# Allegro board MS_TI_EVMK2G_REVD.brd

Outline 305.63 x 258 mm; copper layers: TOP, L02_GND1, L03_SIG1, L04_GND2, L05_PWR1, L06_PWR2, L07_GND3, L08_SIG2, L09_GND4, BOTTOM. Coordinates in mm from the lower left corner of the outline.
Outline path: 0,7 1.27,7 ; 0.64,251 0.64,256.8 arc(0.99,257.65) 1.83,258 304.43,258 arc(305.28,257.65) 305.63,256.8 305.63,251 ; 0.64,251 305.63,251 ; 0.64,251 0.64,7 ; 305.63,251 305.63,7 ; 0.64,7 0.64,1.2 arc(0.99,0.35) 1.83,0 304.43,0 arc(305.28,0.35) 305.63,1.2 305.63,7 ; 0.64,7 305.63,7 ; 0.64,6.36 0.64,7.63 ; 77.68,7 77.68,5 95.41,5 95.41,7 ; 159.66,7 159.66,4.97 159.67,4.97 182.04,4.97 182.04,6.93 ; 188.99,7 188.99,4.97 200.5,4.97 200.5,7 ; 207.02,7.05 207.02,5.03 224.66,5.03 224.66,7.05 ; 231.49,7 231.49,4.97 293.03,4.97 293.03,7

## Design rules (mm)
net group 1P8V_EN: nets 1P8V_EN N20088355
net group 24MHZ_LVCMOS_USB0_CLK: nets 24MHZ_LVCMOS_USB0_CLK SOC_USB0_XO
net group 24MHZ_LVCMOS_USB1_CLK: nets 24MHZ_LVCMOS_USB1_CLK SOC_USB1_XO
net group 24MHZ_LVDS_N: nets 24MHZ_LVDS_N SOC_SYSCLKN
net group 24MHZ_LVDS_P: nets 24MHZ_LVDS_P SOC_SYSCLKP
net group 100MHZ_HCSL: nets 100MHZ_HCSL_N 100MHZ_HCSL_P
net group 100MHZ_LVDS_N: nets 100MHZ_LVDS_N DDR_CLKN_LVDS_100MHZ
net group 100MHZ_LVDS_P: nets 100MHZ_LVDS_P DDR_CLKP_LVDS_100MHZ
net group 250MHZ_LVDS_CPTS_REF_CLKN: nets 250MHZ_LVDS_CPTS_REF_CLKN 250MHZ_LVDS_N
net group 250MHZ_LVDS_CPTS_REF_CLKP: nets 250MHZ_LVDS_CPTS_REF_CLKP 250MHZ_LVDS_P
net group BMC_BLUE_LED: nets BMC_BLUE_LED N14119383
net group BMC_GPIO0: nets BMC_GPIO0 N19771684
net group BMC_GPIO1: nets BMC_GPIO1 N19771691
net group BMC_GPIO3: nets BMC_GPIO3 N19771705
net group BMC_GPIO4: nets BMC_GPIO4 N19771712
net group BMC_GPIO5: nets BMC_GPIO5 N19771719
net group BMC_GPIO6: nets BMC_GPIO6 N19771726
net group BMC_GREEN_LED: nets BMC_GREEN_LED N14119875
net group BMC_I2C1_SCL: nets BMC_I2C1_SCL N19935623
net group BMC_I2C1_SDA: nets BMC_I2C1_SDA N19935654
net group BMC_SPI0_CLK: nets BMC_SPI0_CLK N19776412
net group BMC_UART1_RX: nets BMC_UART1_RX N20334677
net group BMC_UART1_TX: nets BMC_UART1_TX N20334698
net group BMC_XOSC0: nets BMC_XOSC0 BMC_XOSC0_R
net group BUF_ETH_RSTN: nets BUF_ETH_RSTN ETH_RSTN_AND
net group BUF_I2C1_SCL: nets BUF_I2C1_SCL N19351417
net group BUF_I2C1_SDA: nets BUF_I2C1_SDA N19351424
net group BUF_MCASP2AXR3: nets BUF_MCASP2AXR3 N14061510
net group BUF_MIPI_TCK: nets BUF_MIPI_TCK N23802386
net group BUF_TXVR_RXD: nets BUF_TXVR_RXD N16801982
net group BUF_TXVR_TXD: nets BUF_TXVR_TXD N16801984
net group BUF_XDS_TCK: nets BUF_XDS_TCK N18323233
net group BUFF_DSS_DE: nets BUFF_DSS_DE SOC_DSS_DE
net group BUFF_DSSDATA0: nets BUFF_DSSDATA0 SOC_DSSDATA0
net group BUFF_DSSDATA1: nets BUFF_DSSDATA1 SOC_DSSDATA1
net group BUFF_DSSDATA2: nets BUFF_DSSDATA2 SOC_DSSDATA2
net group BUFF_DSSDATA3: nets BUFF_DSSDATA3 SOC_DSSDATA3
net group BUFF_DSSDATA4: nets BUFF_DSSDATA4 SOC_DSSDATA4
net group BUFF_DSSDATA5: nets BUFF_DSSDATA5 SOC_DSSDATA5
net group BUFF_DSSHSYNC: nets BUFF_DSSHSYNC SOC_DSSHSYNC
net group BUFF_DSSPCLK: nets BUFF_DSSPCLK SOC_DSSPCLK
net group BUFF_DSSVSYNC: nets BUFF_DSSVSYNC SOC_DSSVSYNC
net group CAN1: nets N19508331 N19508333
net group COM_AUD_CLK: nets COM_AUD_CLK WL_MCASP2_ACLKR
net group COM_AUD_FSYNC: nets COM_AUD_FSYNC WL_MCASP2_FSR
net group COM_AUD_IN: nets COM_AUD_IN WL_MCASP2_AXR1
net group COM_AUD_OUT: nets COM_AUD_OUT WL_MCASP2_AXR4
net group COM_BTRST: nets COM_BTRST WL_BT_EN
net group COM_BTUARTCTS: nets COM_BTUARTCTS WL_UART1_RTSN
net group COM_BTUARTRTS: nets COM_BTUARTRTS WL_UART1_CTSN
net group COM_BTUARTRX: nets COM_BTUARTRX WL_UART1_TXD
net group COM_BTUARTTX: nets COM_BTUARTTX WL_UART1_RXD
net group COM_SLOW_CLK: nets COM_SLOW_CLK WL_WLAN_CLK
net group COM_WL_IRQ: nets COM_WL_IRQ WL_WLAN_IRQ
net group COM_WL_RST: nets COM_WL_RST WL_WLAN_EN
net group CPLD_A0: nets CPLD_A0 EMA_A0
net group CPLD_A1: nets CPLD_A1 EMA_A1
net group CPLD_A2: nets CPLD_A2 EMA_A2
net group CPLD_A3: nets CPLD_A3 EMA_A3
net group CPLD_BIO_0: nets CPLD_BIO_0 GP4-0
net group CPLD_BIO_1: nets CPLD_BIO_1 GP4-1
net group CPLD_BIO_2: nets CPLD_BIO_2 GP4-2
net group CPLD_CSN: nets CPLD_CSN N17109206
net group CPLD_D0: nets CPLD_D0 EMA_D0
net group CPLD_D1: nets CPLD_D1 EMA_D1
net group CPLD_RDN: nets CPLD_RDN N17108922
net group CPLD_TCK: nets CPLD_TCK N17113205
net group CPLD_WEN: nets CPLD_WEN N17108924
net group CVDD_EN: nets CVDD_EN N20088352
net group DAT4: nets DAT4 SOC_MMC1_DAT4
net group DAT5: nets DAT5 SOC_MMC1_DAT5
net group DAT6: nets DAT6 SOC_MMC1_DAT6
net group DAT7: nets DAT7 SOC_MMC1_DAT7
net group DBG_EMU0: nets DBG_EMU0 N21115682
net group DBG_EMU1: nets DBG_EMU1 N21115817
net group DBG_RTCK: nets DBG_RTCK RTCK/GP8[0]
net group DIFFPAIR2: nets CP2105_DM CP2105_DP
net group DP1: nets N19508261 N19508263
net group DP3: nets N19510567 N19510569
net group EMA_A4: nets EMA_A4 MEM_A4
net group EMA_A5: nets EMA_A5 MEM_A5
net group EMA_A6: nets EMA_A6 MEM_A6
net group EMA_A7: nets EMA_A7 MEM_A7
net group EMA_A8: nets EMA_A8 MEM_A8
net group EMA_A9: nets EMA_A9 MEM_A9
net group EMA_A10: nets EMA_A10 MEM_A10
net group EMA_A11: nets EMA_A11 MEM_A11
net group EMA_A12: nets EMA_A12 MEM_A12
net group EMA_BA0: nets EMA_BA0 MEM_BA0
net group EMA_BA1: nets EMA_BA1 MEM_BA1
net group EMA_D2: nets EMA_D2 MEM_D2
net group EMA_D3: nets EMA_D3 MEM_D3
net group EMA_D4: nets EMA_D4 MEM_D4
net group EMA_D5: nets EMA_D5 MEM_D5
net group EMA_D6: nets EMA_D6 MEM_D6
net group EMA_D7: nets EMA_D7 MEM_D7
net group EMA_D8: nets EMA_D8 MEM_D8
net group EMA_D9: nets EMA_D9 MEM_D9
net group EMA_D10: nets EMA_D10 MEM_D10
net group EMA_D11: nets EMA_D11 MEM_D11
net group EMA_D12: nets EMA_D12 MEM_D12
net group EMA_D13: nets EMA_D13 MEM_D13
net group EMA_D14: nets EMA_D14 MEM_D14
net group EMA_D15: nets EMA_D15 MEM_D15
net group GND: nets PLL0_VSSA PLL1_VSSA
net group HDMI_CLK: nets HDMI_CLK+ HDMI_CLK-
net group HDMI_TX0: nets HDMI_TX0+ HDMI_TX0-
net group HDMI_TX1: nets HDMI_TX1+ HDMI_TX1-
net group HDMI_TX2: nets HDMI_TX2+ HDMI_TX2-
net group LCD_DCLK: nets LCD_DCLK N20247908
net group LCD_EN: nets LCD_EN N20391651
net group LCD_HD: nets LCD_HD N17473267
net group LCD_VD: nets LCD_VD N20273568
net group MEM_CASN: nets MEM_CASN N17108899
net group MEM_CKE: nets MEM_CKE N17110913
net group MEM_CLK: nets MEM_CLK N17110905
net group MEM_CS0N: nets MEM_CS0N N17108888
net group MEM_RASN: nets MEM_RASN N17110918
net group MEM_WE_DQM0N: nets MEM_WE_DQM0N N17109930
net group MEM_WE_DQM1N: nets MEM_WE_DQM1N N17109932
net group MIPI_EMU_RTCK: nets MIPI_EMU_RTCK MIPI_RTCK
net group MIPI_TDI: nets MIPI_TDI MIPI_TDI_R
net group MIPI_TDO: nets MIPI_TDO MIPI_TDO_R
net group MIPI_TMS: nets MIPI_TMS MIPI_TMS_R
net group MIPI_TRGRSTZ: nets MIPI_TRGRSTZ N17217348
net group MIPI_TRST#: nets MIPI_TRST# MIPI_TRST#_R
net group N14115400: nets N14115400 N20324951
net group N16781633: nets N16781633 N16781680
net group N17255053: nets N17255053 N17255055
net group N17255071: nets N17255071 N17255073
net group N17556024: nets N17556024 N17557462
net group N17556776: nets N17556776 N17556884
net group N18024893: nets N18024893 N20324932
net group N19636243: nets N19636243 N19636350
net group N19636273: nets N19636273 N19636291
net group N21997071: nets N21997071 N21997073
net group NRESPWRON2: nets N20088492 NRESPWRON2
net group PCI_CON_PORZ: nets N18214699 PCI_CON_PORZ
net group PCIE_CLK_HCSL_100MHZ: nets PCIE_CLKN_HCSL_100MHZ PCIE_CLKP_HCSL_100MHZ
net group PCIE_CLKN_CML_100MHZ: nets N22048912 PCIE_CLKN_CML_100MHZ
net group PCIE_CLKP_CML_100MHZ: nets N22048902 PCIE_CLKP_CML_100MHZ
net group PCIEI_RSTN: nets N18211886 PCIEI_RSTN
net group PMIC_GPIO2: nets N20088340 PMIC_GPIO2
net group SD_LP2996A: nets N21320308 SD_LP2996A
net group SEC_REFN: nets N21185356 SEC_REFN
net group SEC_REFP: nets N21185385 SEC_REFP
net group SEL_HDMIN: nets SEL_HDMIN SEL_HDMIN_GPIO
net group SOC_MCASP0ACLKR: nets N19368179 SOC_MCASP0ACLKR
net group SOC_MCASP0ACLKX: nets N19368284 SOC_MCASP0ACLKX
net group SOC_MCASP0AHCLKR: nets N19368226 SOC_MCASP0AHCLKR
net group SOC_MCASP0AMUTE: nets N19367970 SOC_MCASP0AMUTE
net group SOC_MCASP0AXR0: nets N19367736 SOC_MCASP0AXR0
net group SOC_MCASP0AXR1: nets N19367738 SOC_MCASP0AXR1
net group SOC_MCASP0AXR2: nets N19367748 SOC_MCASP0AXR2
net group SOC_MCASP0AXR3: nets N19367766 SOC_MCASP0AXR3
net group SOC_MCASP0AXR4: nets N19367768 SOC_MCASP0AXR4
net group SOC_MCASP0AXR5: nets N19367778 SOC_MCASP0AXR5
net group SOC_MCASP0AXR6: nets N19367788 SOC_MCASP0AXR6
net group SOC_MCASP0AXR7: nets N19367798 SOC_MCASP0AXR7
net group SOC_MCASP0AXR8: nets N19367816 SOC_MCASP0AXR8
net group SOC_MCASP0AXR9: nets N19367818 SOC_MCASP0AXR9
net group SOC_MCASP0AXR12: nets N19367846 SOC_MCASP0AXR12
net group SOC_MCASP0AXR13: nets N19367848 SOC_MCASP0AXR13
net group SOC_MCASP0AXR14: nets N19367866 SOC_MCASP0AXR14
net group SOC_MCASP0AXR15: nets N19367868 SOC_MCASP0AXR15
net group SOC_MCASP0FSR: nets N19368123 SOC_MCASP0FSR
net group SOC_MCASP0FSX: nets N19368147 SOC_MCASP0FSX
net group SOC_MCASP1ACLKR: nets N19368850 SOC_MCASP1ACLKR
net group SOC_MCASP1ACLKX: nets N19368786 SOC_MCASP1ACLKX
net group SOC_MCASP1AHCLKR: nets N19368882 SOC_MCASP1AHCLKR
net group SOC_MCASP1AXR0: nets N19368587 SOC_MCASP1AXR0
net group SOC_MCASP1AXR1: nets N19368605 SOC_MCASP1AXR1
net group SOC_MCASP1AXR2: nets N19368607 SOC_MCASP1AXR2
net group SOC_MCASP1AXR3: nets N19368625 SOC_MCASP1AXR3
net group SOC_MCASP1AXR4: nets N19368627 SOC_MCASP1AXR4
net group SOC_MCASP1AXR5: nets N19368645 SOC_MCASP1AXR5
net group SOC_MCASP1AXR6: nets N19368655 SOC_MCASP1AXR6
net group SOC_MCASP1AXR7: nets N19368657 SOC_MCASP1AXR7
net group SOC_MCASP1AXR8: nets N19368675 SOC_MCASP1AXR8
net group SOC_MCASP1AXR9: nets N19368677 SOC_MCASP1AXR9
net group SOC_MCASP1FSR: nets N19368946 SOC_MCASP1FSR
net group SOC_MCASP1FSX: nets N19368978 SOC_MCASP1FSX
net group SOC_MCASP2ACLKR: nets N19369349 SOC_MCASP2ACLKR
net group SOC_MCASP2ACLKX: nets N19369390 SOC_MCASP2ACLKX
net group SOC_MCASP2AHCLKR: nets N19369435 SOC_MCASP2AHCLKR
net group SOC_MCASP2AHCLKX: nets N19369467 SOC_MCASP2AHCLKX
net group SOC_MCASP2AXR1: nets N19369157 SOC_MCASP2AXR1
net group SOC_MCASP2AXR2: nets N19369167 SOC_MCASP2AXR2
net group SOC_MCASP2AXR3: nets N19369177 SOC_MCASP2AXR3
net group SOC_MCASP2AXR4: nets N19369187 SOC_MCASP2AXR4
net group SOC_MCASP2AXR5: nets N19369197 SOC_MCASP2AXR5
net group SOC_MCASP2FSR: nets N19369503 SOC_MCASP2FSR
net group SOC_MCASP2FSX: nets N19369544 SOC_MCASP2FSX
net group SOC_MLB_PCLK: nets SOC_MLB_PCLKN SOC_MLB_PCLKP
net group SOC_MLB_PDATD: nets SOC_MLB_PDATDN SOC_MLB_PDATDP
net group SOC_MMC0_CLK: nets SOC_MMC0_CLK SOC_MMC0_CLK_R
net group SOC_MMC0_CMD: nets SOC_MMC0_CMD SOC_MMC0_CMD_R
net group SOC_MMC0_DAT0: nets SOC_MMC0_DAT0 SOC_MMC0_DAT0_R
net group SOC_MMC0_DAT1: nets SOC_MMC0_DAT1 SOC_MMC0_DAT1_R
net group SOC_MMC0_DAT2: nets SOC_MMC0_DAT2 SOC_MMC0_DAT2_R
net group SOC_MMC0_DAT3: nets SOC_MMC0_DAT3 SOC_MMC0_DAT3_R
net group SOC_PCIE_RXN0: nets SOC_PCIE_RXN0 SOC_PCIE_RXN0_C
net group SOC_PCIE_RXP0: nets SOC_PCIE_RXP0 SOC_PCIE_RXP0_C
net group SOC_PCIE_TX: nets SOC_PCIE_TXN0 SOC_PCIE_TXP0
net group SOC_PCIE_TX_C: nets SOC_PCIE_TXN0_C SOC_PCIE_TXP0_C
net group SOC_PLL_LOCK: nets N19749727 SOC_PLL_LOCK
net group SOC_RESETSTATZ: nets N19749933 SOC_RESETSTATZ
net group SOC_RGMII_RXCLK: nets SOC_RGMII_RXCLK SOC_RGMII_RXCLK_R
net group SOC_RGMII_RXCTL: nets SOC_RGMII_RXCTL SOC_RGMII_RXCTL_R
net group SOC_RGMII_RXD0: nets SOC_RGMII_RXD0 SOC_RGMII_RXD0_R
net group SOC_RGMII_RXD1: nets SOC_RGMII_RXD1 SOC_RGMII_RXD1_R
net group SOC_RGMII_RXD2: nets SOC_RGMII_RXD2 SOC_RGMII_RXD2_R
net group SOC_RGMII_RXD3: nets SOC_RGMII_RXD3 SOC_RGMII_RXD3_R
net group SOC_RGMII_TXCLK: nets SOC_RGMII_TXCLK SOC_RGMII_TXCLK_R
net group SOC_RGMII_TXCTL: nets SOC_RGMII_TXCTL SOC_RGMII_TXCTL_R
net group SOC_RGMII_TXD0: nets SOC_RGMII_TXD0 SOC_RGMII_TXD0_R
net group SOC_RGMII_TXD1: nets SOC_RGMII_TXD1 SOC_RGMII_TXD1_R
net group SOC_RGMII_TXD2: nets SOC_RGMII_TXD2 SOC_RGMII_TXD2_R
net group SOC_RGMII_TXD3: nets SOC_RGMII_TXD3 SOC_RGMII_TXD3_R
net group SOC_SPI0_CLK: nets N19935221 SOC_SPI0_CLK
net group SOC_SPI1_CLK: nets SOC_SPI1_CLK SOC_SPI1_CLK_R
net group SOC_SPI2_CLK: nets N19935328 SOC_SPI2_CLK
net group SOC_SPI3_CLK: nets N19776321 SOC_SPI3_CLK
net group SOC_SPI3_SCS0: nets SOC_SPI3_SCS0 SOC_SPI3_SCS0_R
net group SOC_USB1_ID: nets SOC_USB1_ID USB1_CONN_ID
net group T_RTCK: nets T_RTCK URTCK
net group T_TCK: nets T_TCK UTCK
net group T_TDI: nets T_TDI UTDI
net group T_TDIS: nets T_TDIS UTDIS
net group T_TMS: nets T_TMS UTMS
net group T_TRST_N: nets T_TRST_N UTRSTN
net group TPS_INT1: nets N20088495 TPS_INT1
net group UART0_TXVR_EN: nets N18091435 UART0_TXVR_EN
net group USB1_: nets USB0_CONN_DM USB0_CONN_DP
net group UTDO: nets UTDO XDS200_TDO
net group VCC3V3_LCD: nets N16781762 VCC3V3_LCD
net group VCC5V0_LCD: nets N16781794 VCC5V0_LCD
net group VHDMI_IOVCC: nets N14056401 VHDMI_IOVCC
net group XDS200_SPI1_CLK: nets N17255146 XDS200_SPI1_CLK
net group XDS_SYS_RESETN: nets N17289768 XDS_SYS_RESETN
net group AUD_MCLK_R: nets AUD_MCLK_R HDMI_AUDIO_MSTRCLK N22896196
net group BMC_I2C0_SCL: nets BMC_I2C0_SCL N19643490 PMBUS_SCL
net group BMC_I2C0_SDA: nets BMC_I2C0_SDA N19643422 PMBUS_SDA
net group BMC_JTAG_TCK: nets BMC_JTAG_TCK JTAG_RTCK N14084176
net group BMC_SPI0_MISO: nets BMC_SPI0_MISO BMC_SPI0_MOSI N17177920 N18163620
net group BMC_SPI1_MOSI: nets BMC_SPI1_MOSI N18029281 N18029296
net group BUF_MMC1_CLK: nets BUF_MMC1_CLK N26217961 SOC_MMC1_CLK SOC_MMC1_CLK_R
net group BUF_MMC1_CMD: nets BUF_MMC1_CMD N26217993 SOC_MMC1_CMD SOC_MMC1_CMD_R
net group BUF_MMC1_DAT0: nets BUF_MMC1_DAT0 DAT0 SOC_MMC1_DAT0 SOC_MMC1_DAT0_R
net group BUF_MMC1_DAT1: nets BUF_MMC1_DAT1 DAT1 SOC_MMC1_DAT1 SOC_MMC1_DAT1_R
net group BUF_MMC1_DAT2: nets BUF_MMC1_DAT2 DAT2 SOC_MMC1_DAT2 SOC_MMC1_DAT2_R
net group BUF_MMC1_DAT3: nets BUF_MMC1_DAT3 DAT3 SOC_MMC1_DAT3 SOC_MMC1_DAT3_R
net group BUFF_DSSDATA6: nets BUFF_DSSDATA6 MIPI_EMU19 SOC_DSSDATA6
net group BUFF_DSSDATA7: nets BUFF_DSSDATA7 MIPI_EMU18 SOC_DSSDATA7
net group BUFF_DSSDATA8: nets BUFF_DSSDATA8 MIPI_EMU17 SOC_DSSDATA8
net group BUFF_DSSDATA9: nets BUFF_DSSDATA9 MIPI_EMU16 SOC_DSSDATA9
net group BUFF_DSSDATA10: nets BUFF_DSSDATA10 MIPI_EMU15 SOC_DSSDATA10
net group BUFF_DSSDATA11: nets BUFF_DSSDATA11 MIPI_EMU14 SOC_DSSDATA11
net group BUFF_DSSDATA12: nets BUFF_DSSDATA12 MIPI_EMU13 SOC_DSSDATA12
net group BUFF_DSSDATA13: nets BUFF_DSSDATA13 MIPI_EMU12 SOC_DSSDATA13
net group BUFF_DSSDATA14: nets BUFF_DSSDATA14 MIPI_EMU11 SOC_DSSDATA14
net group BUFF_DSSDATA15: nets BUFF_DSSDATA15 MIPI_EMU10 SOC_DSSDATA15
net group BUFF_DSSDATA16: nets BUFF_DSSDATA16 MIPI_EMU09 SOC_DSSDATA16
net group BUFF_DSSDATA17: nets BUFF_DSSDATA17 MIPI_EMU08 SOC_DSSDATA17
net group BUFF_DSSDATA18: nets BUFF_DSSDATA18 MIPI_EMU07 SOC_DSSDATA18
net group BUFF_DSSDATA19: nets BUFF_DSSDATA19 MIPI_EMU06 SOC_DSSDATA19
net group BUFF_DSSDATA20: nets BUFF_DSSDATA20 MIPI_EMU05 SOC_DSSDATA20
net group BUFF_DSSDATA21: nets BUFF_DSSDATA21 MIPI_EMU04 SOC_DSSDATA21
net group BUFF_DSSDATA22: nets BUFF_DSSDATA22 MIPI_EMU03 SOC_DSSDATA22
net group BUFF_DSSDATA23: nets BUFF_DSSDATA23 MIPI_EMU02 SOC_DSSDATA23
net group CLK32KOUT: nets CLK32KOUT N19442104 WLAN_SLOW_CLK
net group CPLD_BIO_3: nets CPLD_BIO_3 CPLD_TXD1 GP4-3
net group CPLD_BIO_4: nets CPLD_BIO_4 CPLD_RXD1 GP4-4
net group CS2000_CLKIN: nets CS2000_CLKIN SOC_CPTS_TS_COMP SOC_MCASP1AMUTE SOC_MCASP1AMUTE_R
net group DC_BRD_DET: nets DC_BRD_DET N20333845 N22525689 N24555288
net group DDR_DB0: nets DDR_DM0 DDR_DQ0 DDR_DQ1 DDR_DQ2 DDR_DQ3 DDR_DQ4 DDR_DQ5 DDR_DQ6 DDR_DQ7 DDR_DQS0 DDR_DQS0#
net group DDR_DB1: nets DDR_DM1 DDR_DQ8 DDR_DQ9 DDR_DQ10 DDR_DQ11 DDR_DQ12 DDR_DQ13 DDR_DQ14 DDR_DQ15 DDR_DQS1 DDR_DQS1#
net group DDR_DB2: nets DDR_DM2 DDR_DQ16 DDR_DQ17 DDR_DQ18 DDR_DQ19 DDR_DQ20 DDR_DQ21 DDR_DQ22 DDR_DQ23 DDR_DQS2 DDR_DQS2#
net group DDR_DB3: nets DDR_DM3 DDR_DQ24 DDR_DQ25 DDR_DQ26 DDR_DQ27 DDR_DQ28 DDR_DQ29 DDR_DQ30 DDR_DQ31 DDR_DQS3 DDR_DQS3#
net group DDR_DB4: nets DDR_CB00 DDR_CB01 DDR_CB02 DDR_CB03 DDR_CBDQM DDR_CBDQS DDR_CBDQS#
net group DISP_EN: nets DISP_EN SEL_LCD SEL_LCDN SEL_LCDN_GPIO
net group ETHER1_D0_D3: nets ETHER1_D0N ETHER1_D0P ETHER1_D1N ETHER1_D1P ETHER1_D2N ETHER1_D2P ETHER1_D3N ETHER1_D3P
net group HDMI-RGB: nets HDMI_AC_BIAS_EN HDMI_DATA0 HDMI_DATA1 HDMI_DATA2 HDMI_DATA3 HDMI_DATA4 HDMI_DATA5 HDMI_DATA6 HDMI_DATA7 HDMI_DATA8 HDMI_DATA9 HDMI_DATA10 HDMI_DATA11 HDMI_DATA12 HDMI_DATA13 HDMI_DATA14 HDMI_DATA15 HDMI_DATA16 HDMI_DATA17 HDMI_DATA18 HDMI_DATA19 HDMI_DATA20 HDMI_DATA21 HDMI_DATA22 HDMI_DATA23 HDMI_HSYNC HDMI_PCLK HDMI_VSYNC
net group INA_ALERT: nets INA_ALERT N21783594 N21786150 N21786851 N21787536 N21787552
net group LCD: nets LCD_BLUE0 LCD_BLUE1 LCD_BLUE2 LCD_BLUE3 LCD_BLUE4 LCD_BLUE5 LCD_BLUE6 LCD_BLUE7 LCD_GREEN0 LCD_GREEN1 LCD_GREEN2 LCD_GREEN3 LCD_GREEN4 LCD_GREEN5 LCD_GREEN6 LCD_GREEN7 LCD_RED0 LCD_RED1 LCD_RED2 LCD_RED3 LCD_RED4 LCD_RED5 LCD_RED6 LCD_RED7
net group MIPI_TCK: nets MIPI_TCK MIPI_TCK_R SEL_XDS200_INV SOC_TDI SOC_TDO SOC_TMS VCC3V3_MIPI
net group N14092548: nets N14092548
net group N21505605: nets N21505605 N21505608 N21505611
net group PENDING_NETS: nets AUDIO_RSTN AUDIO_RSTN_AND BMC_HIBN BMC_INT1 BMC_ISOL_EN1 BMC_ISOL_EN2 BMC_ISOL_EN3 BMC_ISOL_EN4 BMC_ISOL_EN5 BMC_JTAG_TDI BMC_JTAG_TDO BMC_JTAG_TMS BMC_JTAG_TRSTN BMC_LCD_A0 BMC_LCD_RSTN BMC_OSC0 BMC_OSC1 BMC_PORN BMC_SPI1_CLK BMC_SPI1_CSN BMC_SYSCLKSEL BOOTMODEON BT_EN CDCM_PDN# CDCM_RST CDCM_SPI_CS0 CDCM_SYNC# CLK_REF_SEL COM8_MMC1_CLK COM8_MMC1_CMD COM8_MMC1_DAT0 COM8_MMC1_DAT1 COM8_MMC1_DAT2 COM8_MMC1_DAT3 CPLD_RESETN CPLD_TMS DAC_VOUT DC_BRD_DET_INV DDR_A1 DDR_A2 DDR_A3 DDR_A5 DDR_A6 DDR_A8 DDR_A9 DDR_A11 DDR_A12 DDR_A15 DDR_BA0 DDR_BA1 DDR_CAS# DDR_CE1Z DDR_CKE DDR_CKE1 DDR_CS# DDR_ODT1 DDR_WE# DIR EEPROM_WP EMMC_RSTN EMULED1 EMULED2 ETH_RSTN FB_DCDC FB_LDO2 FLASH_HOLD FLASH_WPN GPIO_EXP_INT HDMI_AUDBCLK HDMI_AUDD0 HDMI_AUDFSX HDMI_AUDMCLK HDMI_INTN HDMI_RSTN HDMI_RSTN_AND INT1 JTAG_PD LDO_PCIE_CAP LDO_USB_CAP MLB_RSTN MODE N14027930 N14056347 N14060684 N14060756 N14060760 N14060764 N14060776 N14060794 N14060830 N14060838 N14152075 N14152267 N16863485 N16909238 N16911821 N17104917 N17104924 N17105134 N17124284 N17124300 N17217726 N17428402 N17556798 N17556932 N17557226 N17557396 N17944399 N17944408 N18055312 N18055326 N18144573 N18147498 N18151943 N18158148 N18158579 N19207451 N19207912 N19207996 N19208525 N19208527 N19208590 N19209091 N19209222 N19355586 N19364584 N19364586 N19364588 N19364600 N19520807 N19521127 N19521129 N19521147 N19521183 N19533446 N19631369 N19631425 N19631427 N19631454 N19631468 N19636076 N19636388 N19636390 N19738237 N19748787 N19752383 N19760880 N19776797 N19776809 N19936542 N19936548 N20088489 N20327049 N20476232 N21316200 N21500371 N21690505 N22048972 N22048974 N22774183 N22774186 N22774189 N22774190 N22774191 N22774198 N23995260 N28005348 N28490068 N28490071 N28490074 N28490080 N196364310 PHY1_LED_ACTN PHY1_LED_LINKN PLL1_VDDA1V2 PLL_LOCK PMBUS_I2C_EN PMIC_HDRST PMIC_PWRHOLD PWRON_RSTZ QSPI_RSTN QSPI_RSTN_AND RS232_CONN0_RX RS232_CONN0_TX SEL_XDS SOC_BACKLIGHT_PWM SOC_DCAN0_RX SOC_DCAN0_TX SOC_DCAN1_RX SOC_DCAN1_TX SOC_ECAP1_IN_PWM1_OUT SOC_EHRPWM3_SYNCI SOC_EHRPWM3_SYNCO SOC_EHRPWM3A SOC_EHRPWM3B SOC_EHRPWM4A SOC_EHRPWM4B SOC_EHRPWM5A SOC_EHRPWM5B SOC_EHRPWM_TRIPZONE_INPUT3 SOC_EHRPWM_TRIPZONE_INPUT4 SOC_EHRPWM_TRIPZONE_INPUT5 SOC_EMU00 SOC_EMU01 SOC_GPMC_WAIT0 SOC_GPMC_WP# SOC_I2C_EN SOC_MCBSPCLKR SOC_MCBSPCLKX SOC_MCBSPDR SOC_MCBSPDX SOC_MCBSPFSR SOC_MCBSPFSX SOC_MDIO_CLK SOC_MDIO_DATA SOC_MLB_GPIO2 SOC_MLB_PSIGN SOC_MLB_PSIGP SOC_MLBCLK SOC_MLBDAT SOC_MLBSIG SOC_NMIZ SOC_SPI0_MISO SOC_SPI0_MOSI SOC_SPI0_SCS0 SOC_SPI0_SCS1 SOC_SPI1_MISO SOC_SPI1_MOSI SOC_SPI1_SCS0 SOC_SPI2_MISO SOC_SPI2_MOSI SOC_SPI2_SCS0 SOC_SPI3_MISO SOC_SPI3_MOSI SOC_TIMI1 SOC_TIMO1 SOC_TRST# SOC_UART0_CTSN SOC_UART0_RTSN SOC_UART0_RXD SOC_UART0_TXD SOC_UART2_RXD SOC_UART2_TXD SOC_USB0_ID SOC_USB0_VBUSEN SOC_USB1_VBUSEN TEMP_INT TOUCH_INTN TPS65000_PG# TPS_SLEEP TRGRSTZ USB0_VDDA12 USB0_VDDA18 USB1_CONN_DM USB1_CONN_DP UTMSK VBACKUP VCC3V0_BMC_BKL VCC3V0_BMC_LCD VCC3V3_R VCC3V3_WLAN VCC5V0_HDMI VETH1_AVDDL_PLL WLAN_EN WLAN_IRQ XDS200_EMU0 XDS200_EMU1 XDS200_SPI1_SCS[0] XDS200_SPI1_WPN XDS200_SPI_HOLDN
net group POWER: nets 5V_EN 5V_PWRGD AVDDA_ARMPLL AVDDA_DDRPLL AVDDA_DSSPLL AVDDA_ICSSPLL AVDDA_MAINPLL AVDDA_NSSPLL AVDDA_UARTPLL DDR_DVDD18 DVDD18 DVDD_DDRPLL GND_EARTH LDO5_3V3 LDO7_3V3 N14027466 N19525941 PLL0_VDDA1V2 PMIC_PWRON PMIC_VIO VCC0V85 VCC1V8_EMMC VCC3V3_EMMC VCC_BMC_LCD VCC_DDR_VREF VDDAHV VETH1_AVDDL VETH1_DVDDH VETH1_DVDDL VHDMI_CVCC12 VLED+ VLED- VRTC
net group PRSNT#: nets N18192341 PRSNT1# PRSNT#
net group QSP_CLK: nets SOC_QSPI_CSN0 SOC_QSPI_D0 SOC_QSPI_D1 SOC_QSPI_D3
net group SOC_I2C0_SCL: nets N19935032 N21103457 N22366198 SOC_I2C0_SCL
net group SOC_I2C0_SDA: nets N19935028 N21103450 N22366201 SOC_I2C0_SDA
net group SOC_I2C1_SCL: nets N19935173 N19936677 N22367180 SOC_I2C1_SCL
net group SOC_I2C1_SDA: nets N18067178 N19935171 N22367188 SOC_I2C1_SDA
net group SOC_I2C2_SCL: nets N19636469 N21103343 SOC_I2C2_SCL VCNTL0
net group SOC_I2C2_SDA: nets N19636467 N21103341 SOC_I2C2_SDA VCNTL1
net group SOC_LED0: nets N22816587 SOC_LED1 SOC_MCASP0AXR10 SOC_MCASP0AXR10_R
net group SOC_LED1: nets N22816314 SOC_LED0 SOC_MCASP2AXR0 SOC_MCASP2AXR0_R
net group SOC_MCASP0AHCLKX: nets N19368266 N19368922 SOC_MCASP0AHCLKX
net group SOC_MCASP2AMUTE: nets SOC_MCASP2AMUTE SOC_MCASP2AMUTE_R WLAN_TRANS_EN
net group SOC_MMC1_SDWP: nets N26218848 N26218884 SOC_MMC1_SDWP TRANS_EMMC_RSTN
net group SOC_QSPI_CLK: nets N19442180 SOC_QSPI_CLK SOC_QSPI_CLK_R SOC_QSPI_RTCLK
net group USB: nets SOC_USB0_DM SOC_USB0_DP SOC_USB1_DM SOC_USB1_DP XDS_USB_DM XDS_USB_DP
net group VCC3V3_CP2105: nets N27236702
net group VCC3V3_HDMI: nets N14056377 N14057055 VCC3V3_HDMI
nets with their own width: min track width 0.152; nets DGND
nets with their own width: min track width 0.254; nets GND_PCIE

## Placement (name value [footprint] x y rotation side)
C1  0.1uF  [CAP0402]  94.26 116.12 90 top
C2  22uF  [CAP1210]  292.23 208.29 0 top
C3  0.1uF  [CAP0402]  144.02 209.95 0 top
C4  22uF  [CAP1210]  144.27 216.55 180 top
C5  22uF  [CAP1210]  204.44 242.31 180 top
C6  100uF_10V  [CAPT3528B]  143.89 212.99 180 top
C7  10uF  [CAP1210]  251.61 17.67 270 top
C8  10000pF_50V  [CAP0402]  258.09 17.92 90 top
C9  10000pF_50V  [CAP0402]  254.66 18.43 270 top
C10  22uF  [CAP0805]  288.65 95.24 270 top
C11  22uF  [CAP0805]  276.45 95.75 180 top
C12  0.1uF  [CAP0402]  285.6 96 180 top
C13  0.1uF  [CAP0402]  285.6 93.97 0 top
C14  0.1uF  [CAP0402]  136.02 231.15 90 top
C15  1uF  [CAP0402]  193.67 236.23 270 top
C16  22uF  [CAP0805]  282.3 89.4 180 top
C17  0.1uF  [CAP0402]  281.9 92.06 90 top
C18  0.1uF  [CAP0402]  132.08 222.65 0 top
C19  1uF  [CAP0402]  189.48 232.55 180 top
C20  2.2uF  [CAP1210]  131.57 220.11 180 top
C21  2.2uF  [CAP0402]  189.48 230.9 180 top
C22  22uF_35V  [CAPT7343E]  129.92 215.66 180 top
C23  100uF_35V  [CAPAE_D8CASE]  289.56 214.14 180 top
C24  22uF  [CAP0805]  277.72 102.48 0 top
C25  0.1uF  [CAP0402]  277.47 104.51 180 top
C26  1000pF_50V  [CAP0402]  285.65 98.21 0 top
C27  15pF  [CAP0402]  193.93 228.74 0 top
C28  0.1uF  [CAP0402]  255.4 94.88 180 top
C29  22pF  [CAP0402]  273.53 98.03 0 top
C30  0.1uF  [CAP0402]  268.58 65.34 180 top
C31  1uF  [CAP0402]  122.81 229.76 0 top
C32  1uF  [CAP0603]  58.29 221.33 270 top
C33  0.01uF  [CAP0402]  59.94 221.33 90 top
C34  1uF  [CAP0402]  61.47 221.33 90 top
C35  0.47uF  [CAP0603]  41.53 227.93 90 bottom
C36  0.47uF  [CAP0603]  43.81 227.93 90 bottom
C37  0.47uF  [CAP0603]  45.97 227.93 90 bottom
C38  0.47uF  [CAP0603]  48.13 227.93 90 bottom
C39  0.47uF  [CAP0603]  50.16 227.93 90 bottom
C40  0.1uF  [CAP0402]  24.13 232.81 270 top
C41  0.1uF  [CAP0402]  26.42 232.81 270 top
C42  22uF  [CAP0805]  236.32 36.26 270 bottom
C43  22uF  [CAP0805]  251.43 62.22 90 bottom
C44  0.1uF  [CAP0402]  234.92 50.87 0 bottom
C45  0.1uF  [CAP0402]  234.92 55.56 0 bottom
C46  0.1uF  [CAP0402]  246.51 86.63 90 top
C47  0.1uF  [CAP0402]  248.79 57.04 180 bottom
C48  100uF  [CAP1210]  254.08 216.73 0 top
C49  100uF  [CAP1210]  254.08 220.36 0 top
C50  0.1uF  [CAP0402]  254.13 223.03 0 top
C51  120uF  [CAPAE_ECASE]  209.91 34.64 270 bottom
C52  18pF  [CAP0402]  257.76 54.14 270 top
C53  18pF  [CAP0402]  257.76 57.24 90 top
C54  33pF  [CAP0805]  252.2 54.17 90 top
C55  0.1uF  [CAP0402]  240.61 53.33 90 bottom
C56  0.018uF  [CAP0402]  259.08 217.18 0 top
C57  1uF  [CAP0402]  239.75 40.2 90 top
C58  0.1uF  [CAP0402]  27.18 220.99 90 top
C59  1uF  [CAP0402]  238.23 40.2 90 top
C60  33pF  [CAP0805]  252.17 50.66 270 top
C61  0.1uF  [CAP0402]  240.61 49.47 270 bottom
C62  0.1uF  [CAP0402]  235.58 99.96 0 top
C63  8200pF  [CAP0402]  263.02 218.2 270 top
C64  1000pF_50V  [CAP0402]  253.09 49.6 0 bottom
C65  0.1uF  [CAP0402]  177.16 222.9 90 bottom
C66  1uF  [CAP0402]  253.09 48.07 0 top
C67  0.1uF  [CAP0402]  242.16 46.83 0 bottom
C68  0.1uF  [CAP0402]  167.18 219.06 90 bottom
C69  4.7uF  [CAP0603]  72.36 204.94 90 top
C70  0.01uF  [CAP0201]  75.03 196.56 135 bottom
C71  0.1uF  [CAP0402]  234.92 54.04 0 bottom
C72  22pF  [CAP0402]  86.72 203.24 90 top
C73  1uF  [CAP0402]  253.09 44.39 0 top
C74  0.1uF  [CAP0402]  268.86 213.76 0 top
C75  10uF  [CAP1210]  269.75 216.3 0 top
C76  10uF  [CAP1210]  269.88 211.22 0 top
C78  1000pF_50V  [CAP0402]  253.09 40.71 0 top
C79  0.01uF  [CAP0402]  248.77 50.87 90 bottom
C80  22pF  [CAP0402]  86.72 200.22 270 top
C81  10uF  [CAP0805]  294.34 241.85 180 top
C82  0.1uF  [CAP0402]  301.12 239.92 180 bottom
C83  0.1uF  [CAP0402]  180.87 210.23 270 bottom
C84  0.1uF  [CAP0402]  168.5 210.38 270 top
C85  0.1uF  [CAP0402]  244.45 40.2 90 top
C86  0.1uF  [CAP0402]  241.4 40.2 90 top
C87  0.1uF  [CAP0402]  236.58 40.2 90 top
C88  1uF  [CAP0402]  238.23 40.2 90 bottom
C89  0.1uF  [CAP0402]  239.75 40.2 90 bottom
C90  0.1uF  [CAP0402]  241.27 36.64 90 top
C91  3.3uF  [CAP0603]  83.57 197.25 0 top
C92  0.01uF  [CAP0402]  66.55 197.12 180 top
C93  0.01uF  [CAP0402]  83.44 195.59 0 top
C94  0.01uF  [CAP0402]  247.75 45.53 180 bottom
C95  10uF  [CAP1210]  240.79 190.51 90 top
C96  1uF  [CAP0603]  233.93 190.39 90 top
C97  1uF  [CAP0603]  235.97 190.39 90 top
C98  1uF  [CAP0603]  237.87 190.39 90 top
C99  0.1uF  [CAP0402]  243.51 190.08 270 top
C100  4.7uF  [CAP0603]  116.97 206.14 0 bottom
C101  330uF_6.3V  [CAPT7343D]  263.78 189.24 0 top
C102  0.01uF  [CAP0201]  74.24 195.8 315 bottom
C103  0.1uF  [CAP0402]  117.22 207.91 180 bottom
C104  15pF  [CAP0402]  240.54 241.16 90 top
C105  4.7uF  [CAP0603]  173.46 184.34 0 bottom
C106  0.1uF  [CAP0402]  84.58 183.78 0 top
C107  4.7uF  [CAP1206]  251.82 173.6 270 bottom
C108  4.7uF  [CAP1206]  247.5 182.89 180 top
C109  0.1uF  [CAP0402]  84.58 181.88 180 top
C110  0.1uF  [CAP0402]  238 181.75 90 top
C111  10uF  [CAP0805]  240.03 181.5 90 top
C112  0.1uF  [CAP0402]  250.95 179.97 180 top
C113  4.7uF  [CAP0603]  172.08 175.47 270 top
C114  0.1uF  [CAP0402]  247.65 180.48 0 top
C116  2.2uF  [CAP0402]  255.4 178.83 0 top
C117  100uF  [CAP1210]  121.67 200.67 90 top
C118  0.1uF  [CAP0402]  118.87 200.17 270 bottom
C121  0.1uF  [CAP0402]  255.4 177.18 180 top
C122  0.1uF  [CAP0402]  43.31 179.85 180 top
C123  10uF  [CAP0805]  234.19 175.91 270 top
C124  0.1uF  [CAP0402]  236.35 175.66 270 top
C125  0.1uF  [CAP0402]  238.38 175.66 270 top
C126  0.1uF  [CAP0402]  251.46 175.53 180 top
C127  22pF  [CAP0402]  258.7 176.93 270 top
C129  0.1uF  [CAP0402]  118.75 196.99 180 top
C130  0.1uF  [CAP0402]  114.43 196.99 0 top
C131  0.1uF  [CAP0402]  56.9 173.75 0 top
C132  22pF  [CAP0402]  258.75 173.75 90 top
C133  0.01uF  [CAP0402]  176.78 198.84 90 top
C134  0.1uF  [CAP0402]  56.9 171.85 180 top
C135  47uF  [CAP1206]  116.59 193.69 270 top
C136  0.1uF  [CAP0402]  84.84 171.59 0 top
C137  0.1uF  [CAP0402]  236.35 171.59 90 top
C138  0.1uF  [CAP0402]  238.35 171.77 90 top
C140  10uF  [CAP0805]  234.19 171.34 90 top
C141  0.1uF  [CAP0402]  258.95 170.32 270 top
C142  10uF  [CAP0805]  260.86 170.19 270 top
C143  0.1uF  [CAP0402]  84.84 170.07 180 top
C144  0.22uF  [CAP0402]  178.3 184.85 270 bottom
C145  0.22uF  [CAP0402]  178.93 189.82 90 bottom
C146  4.7uF  [CAP0603]  184.4 183.47 0 top
C147  0.1uF  [CAP0402]  195.51 168.56 180 top
C148  10uF  [CAP0805]  238 166 270 top
C149  0.1uF  [CAP0402]  239.9 165.88 270 top
C150  0.1uF  [CAP0402]  243.97 165.62 90 top
C151  0.1uF  [CAP0402]  245.75 165.62 90 top
C152  0.1uF  [CAP0402]  247.4 165.62 90 top
C154  10uF  [CAP0805]  252.73 163.72 180 top
C155  0.1uF  [CAP0402]  252.73 161.81 180 top
C156  4.7uF  [CAP1206]  242.82 160.54 270 top
C157  2.2uF  [CAP0402]  245.75 160.54 270 top
C158  2.2uF  [CAP0402]  248.41 160.54 270 top
C159  0.1uF  [CAP0402]  203.56 179.03 270 bottom
C160  2.2uF  [CAP0402]  235.33 159.91 270 top
C161  0.1uF  [CAP0402]  236.98 159.91 90 top
C162  0.1uF  [CAP0402]  228.88 99.1 180 top
C163  2.2uF  [CAP0402]  238.76 158.51 270 top
C164  0.1uF  [CAP0402]  240.41 158.51 90 top
C165  0.1uF  [CAP0402]  228.88 100.62 180 top
C166  22uF  [CAP1210]  292.99 153.94 180 top
C167  0.1uF  [CAP0402]  294 151.4 180 top
C168  8.2pF  [CAP0402]  211.71 85.23 90 top
C169  10uF  [CAP0805]  293.62 145.3 180 top
C170  0.1uF  [CAP0402]  184.28 155.08 90 top
C171  0.1uF  [CAP0402]  182.75 155.08 90 top
C172  100uF  [CAP1210]  172.72 145.68 90 top
C173  0.1uF  [CAP0402]  293.88 143.52 180 top
C174  0.1uF  [CAP0201]  173.33 137.2 270 bottom
C175  0.1uF  [CAP0201]  179.88 129.94 0 bottom
C176  0.1uF  [CAP0201]  175.16 129.83 0 bottom
C177  100uF  [CAP1210]  176.25 154.55 180 top
C178  0.1uF  [CAP0402]  166.75 139.21 270 top
C179  0.1uF  [CAP0402]  168.27 139.21 270 top
C180  0.01uF  [CAP0201]  172.52 137.2 90 bottom
C181  0.1uF  [CAP0201]  171.7 135.4 90 bottom
C182  0.1uF  [CAP0201]  172.85 139.21 270 top
C183  0.1uF  [CAP0201]  164.97 134 270 bottom
C184  0.01uF  [CAP0201]  179.88 129.2 0 bottom
C185  0.1uF  [CAP0402]  169.8 139.21 270 top
C187  0.1uF  [CAP0402]  165.23 139.21 270 top
C188  0.1uF  [CAP0201]  173.02 121 180 bottom
C189  100uF  [CAP1210]  154.69 136.49 180 bottom
C190  0.1uF  [CAP0201]  155.32 131.92 0 bottom
C191  0.1uF  [CAP0201]  174.09 119.34 315 bottom
C192  0.1uF  [CAP0201]  155.32 132.73 0 bottom
C193  0.1uF  [CAP0201]  174.14 117.67 135 bottom
C194  0.1uF  [CAP0201]  172.01 118.66 180 bottom
C195  0.1uF  [CAP0201]  170.81 116.22 135 bottom
C196  0.1uF  [CAP0201]  175.62 118.2 270 bottom
C197  0.1uF  [CAP0201]  167.72 106.39 90 bottom
C198  0.1uF  [CAP0201]  161.62 117.15 180 bottom
C199  0.1uF  [CAP0201]  162.81 125.16 0 bottom
C200  0.1uF  [CAP0201]  171.53 114.7 315 bottom
C201  1uF  [CAP0402]  177.52 144.24 90 bottom
C202  0.01uF  [CAP0201]  156.72 117.49 270 top
C203  0.1uF  [CAP0201]  154.3 122.82 180 top
C204  100uF  [CAP1210]  180.06 144.9 90 bottom
C205  100uF  [CAP1210]  191.31 143.68 90 bottom
C206  1uF  [CAP0402]  189.74 92.6 180 top
C207  1uF  [CAP0204]  188.77 144.24 90 bottom
C208  0.1uF  [CAP0201]  154.3 125.87 180 top
C209  0.1uF  [CAP0201]  154.3 127.4 0 top
C210  0.01uF  [CAP0201]  183.46 126.33 0 bottom
C211  0.1uF  [CAP0201]  178 124.2 45 bottom
C212  0.1uF  [CAP0201]  169.34 117.67 135 bottom
C213  1uF  [CAP0402]  191.77 89.55 270 top
C214  100uF  [CAP1210]  216.46 148.02 0 top
C215  0.1uF  [CAP0201]  175.95 115.25 0 bottom
C216  0.01uF  [CAP0201]  168.83 118.68 180 bottom
C217  0.01uF  [CAP0201]  183.11 123.03 0 bottom
C218  0.1uF  [CAP0201]  183.11 122.21 0 bottom
C219  0.01uF  [CAP0201]  183.06 119.88 0 bottom
C220  22pF  [CAP0402]  192.53 114.19 90 bottom
C221  0.1uF  [CAP0201]  183.08 119.04 0 bottom
C222  4.7uF  [CAP0603]  44.27 80.33 90 top
C223  22pF  [CAP0402]  192.53 117.36 270 bottom
C224  0.1uF  [CAP0402]  192.25 109.95 180 top
C225  0.1uF  [CAP0402]  196.22 109.11 180 top
C226  0.1uF  [CAP0201]  161.8 114.09 180 bottom
C227  100uF  [CAP1210]  154.3 129.94 180 top
C228  0.1uF  [CAP0201]  172.44 116.25 45 bottom
C229  0.1uF  [CAP0402]  196.22 107.84 180 top
C230  0.1uF  [CAP0402]  154.3 122.82 180 bottom
C231  0.1uF  [CAP0402]  192.25 106.9 180 top
C232  22pF  [CAP0402]  156.36 112.56 90 bottom
C233  10uF  [CAP0805]  145.92 104.15 180 top
C234  22pF  [CAP0402]  156.36 109.49 270 bottom
C235  4.7uF  [CAP0805]  44.65 71.57 270 top
C236  0.1uF  [CAP0402]  145.67 102.38 180 top
C237  0.1uF  [CAP0201]  172.44 105.04 180 bottom
C238  0.1uF  [CAP0402]  140.21 101.11 90 top
C239  10uF  [CAP0805]  142.62 101.36 270 top
C240  1uF  [CAP0402]  145.67 100.85 180 top
C242  0.1uF  [CAP0201]  167.13 109.87 180 bottom
C243  0.1uF  [CAP0201]  178.05 105.3 270 bottom
C244  0.1uF  [CAP0201]  169.29 121.81 0 bottom
C246  0.1uF  [CAP0201]  168.53 115.84 90 bottom
C247  0.1uF  [CAP0201]  173.05 141.47 270 bottom
C248  0.1uF  [CAP0201]  174.19 122.82 225 bottom
C249  0.01uF  [CAP0201]  168.07 102.1 270 bottom
C250  0.01uF  [CAP0201]  175.39 102.28 270 top
C251  1uF  [CAP0204]  182.45 96.76 270 bottom
C252  0.1uF  [CAP0201]  180.34 123.87 90 bottom
C253  0.1uF  [CAP0201]  169.29 114.06 270 bottom
C254  470pF  [CAP0402]  141.86 97.93 90 top
C255  10uF  [CAP0805]  149.99 99.96 180 top
C256  10uF  [CAP0805]  34.36 65.71 90 top
C257  0.01uF  [CAP0402]  36.13 65.46 90 top
C258  0.01uF  [CAP0201]  164.72 102.25 270 top
C259  0.1uF  [CAP0201]  163.58 102.25 90 top
C260  0.1uF  [CAP0201]  173.18 114.65 315 bottom
C261  0.1uF  [CAP0201]  174.65 102.28 90 top
C262  100pF  [CAP0603]  145.03 96.71 90 top
C263  0.1uF  [CAP0201]  171.7 121.1 225 bottom
C264  1uF  [CAP0402]  192.25 108.4 0 top
C265  1uF  [CAP0402]  193.04 96.53 0 top
C266  0.1uF  [CAP0402]  149.73 98.19 180 top
C267  100uF  [CAP1210]  186.59 96.15 270 bottom
C268  0.1uF  [CAP0402]  125.86 99.33 0 top
C269  100pF  [CAP0603]  149.91 94.93 0 top
C271  33pF  [CAP0402]  204.19 93.66 0 top
C272  0.1uF  [CAP0402]  120.27 94.76 90 top
C273  0.01uF  [CAP0402]  121.92 94.76 270 top
C274  15pF  [CAP0402]  133.68 96.55 90 top
C276  1uF  [CAP0402]  146.33 98.57 180 bottom
C277  0.1uF  [CAP0402]  121.29 91.33 270 top
C278  33pF  [CAP0402]  196.77 92.93 180 top
C279  0.1uF  [CAP0402]  183.13 90.95 180 bottom
C280  0.1uF  [CAP0402]  183.13 92.6 0 bottom
C282  1uF  [CAP0402]  135.76 88.41 180 bottom
C283  12pF  [CAP0402]  137.59 80.89 180 top
C284  0.01uF  [CAP0402]  44.58 122.44 180 top
C286  0.1uF  [CAP0402]  14.99 63.64 90 top
C287  1uF  [CAP0402]  173.48 85.49 180 bottom
C288  4.7uF  [CAP0603]  24.64 61.23 180 top
C290  0.1uF  [CAP0402]  15.49 58.82 180 top
C291  1uF  [CAP0402]  15.49 57.29 180 top
C292  10uF  [CAP0805]  110.07 97.55 90 top
C293  0.1uF  [CAP0402]  112.78 94.5 270 top
C294  0.1uF  [CAP0402]  276.14 50.52 0 top
C295  12pF  [CAP0402]  134.54 80.89 0 top
C296  10uF  [CAP0805]  95.25 93.87 180 top
C297  0.01uF  [CAP0402]  151.79 64.51 180 bottom
C298  0.01uF  [CAP0402]  163.12 64.53 0 bottom
C299  0.01uF  [CAP0402]  154.84 64.51 180 bottom
C300  0.01uF  [CAP0402]  130.35 64.12 0 bottom
C301  0.01uF  [CAP0402]  133.91 64.12 180 bottom
C302  0.01uF  [CAP0402]  137.21 64.12 0 bottom
C303  22uF  [CAP0805]  106.05 92.26 270 top
C304  0.01uF  [CAP0402]  110.49 19.47 270 bottom
C305  1uF  [CAP0402]  18.87 56.3 270 top
C306  0.01uF  [CAP0402]  126.75 64.12 180 bottom
C307  0.01uF  [CAP0402]  280.86 60.68 90 bottom
C308  0.1uF  [CAP0402]  23.11 95.77 90 top
C309  0.01uF  [CAP0402]  160.32 64.53 0 bottom
C310  10uF  [CAP0805]  172.52 54.73 0 bottom
C311  0.1uF  [CAP0402]  180.9 55.89 180 top
C312  0.1uF  [CAP0402]  175.95 52.52 90 bottom
C313  100pF  [CAP0402]  44.3 157.29 270 top
C314  100pF  [CAP0402]  39.12 192.75 270 top
C315  22uF  [CAP0805]  89.48 41.63 270 top
C316  10uF  [CAP0805]  276.61 47.26 90 top
C317  100pF  [CAP0402]  39.98 164.53 0 top
C318  0.01uF  [CAP0402]  39.98 157.8 180 top
C319  0.1uF  [CAP0402]  91.26 41.89 270 top
C320  0.01uF  [CAP0402]  35.18 193.26 180 top
C321  100pF  [CAP0402]  35.05 199.86 0 top
C322  0.01uF  [CAP0402]  290.83 35.83 270 top
C323  0.01uF  [CAP0402]  290.83 39.13 270 top
C324  10uF  [CAP0805]  109.25 25.06 270 top
C325  10uF  [CAP0805]  110.59 33.39 0 top
C326  10uF  [CAP0805]  281.81 43.96 0 top
C327  47uF  [CAP1206]  165.4 41.16 0 top
C328  0.1uF  [CAP0402]  268.5 38.01 90 top
C329  0.1uF  [CAP0402]  174.65 48.55 180 bottom
C330  10uF  [CAP0805]  179.93 54.4 0 top
C331  0.1uF  [CAP0402]  41.33 124.53 0 top
C332  0.1uF  [CAP0402]  269.93 38.01 90 top
C333  0.1uF  [CAP0402]  171.48 45.46 270 bottom
C334  22pF  [CAP0402]  165.25 48.43 270 top
C335  22pF  [CAP0402]  165.23 45.38 90 top
C336  10uF  [CAP0805]  165.15 51.58 180 top
C337  10uF  [CAP0805]  173.89 45.23 270 bottom
C338  0.1uF  [CAP0402]  10.77 63.41 90 top
C339  10uF  [CAP0805]  282.83 36.08 0 top
C340  10uF  [CAP0805]  166.5 50.15 180 bottom
C341  0.1uF  [CAP0402]  169.54 45.53 270 top
C342  47uF  [CAP1206]  156.77 47.13 270 bottom
C343  47uF  [CAP1206]  275.34 31.38 90 top
C344  47uF  [CAP1206]  279.27 31.38 90 top
C345  0.1uF  [CAP0402]  24.23 157.8 180 top
C346  10uF  [CAP0805]  176.02 45.25 270 top
C347  0.1uF  [CAP0402]  19.81 193.26 180 top
C348  120uF  [CAPAE_ECASE]  183.59 15.99 90 bottom
C349  0.1uF  [CAP0402]  158.5 20.46 0 bottom
C350  4.7uF  [CAP0603]  211.2 24.07 180 top
C351  0.1uF  [CAP0402]  179.88 23 270 top
C352  3.3uF  [CAP0603]  15.34 149.42 90 top
C353  3.3uF  [CAP0603]  16.13 193.03 90 top
C354  0.1uF  [CAP0402]  201.65 15.64 90 top
C355  4.7uF  [CAP0603]  191.31 13.55 180 top
C356  4.7uF  [CAP0603]  241.81 26.94 90 top
C357  0.1uF  [CAP0402]  117.91 17.24 180 top
C358  0.1uF  [CAP0402]  117.91 15.71 180 top
C359  0.1uF  [CAP0402]  240 26.84 90 top
C360  22uF  [CAP1210]  116.89 20.54 180 top
C361  0.1uF  [CAP0402]  191.13 246.78 270 bottom
C362  10uF  [CAP0805]  192.91 246.39 270 bottom
C363  0.1uF  [CAP0402]  293.85 101.34 180 bottom
C364  0.1uF  [CAP0402]  293.85 102.86 180 bottom
C365  0.1uF  [CAP0402]  205.61 239.66 180 top
C366  0.1uF  [CAP0402]  205.61 238.01 180 top
C367  0.1uF  [CAP0402]  289.53 101.59 270 bottom
C368  0.1uF  [CAP0402]  192.91 241.7 90 bottom
C369  10uF  [CAP0805]  219.58 227.98 0 top
C370  0.1uF  [CAP0402]  219.58 233.19 0 top
C371  0.1uF  [CAP0402]  219.58 231.54 0 top
C372  0.1uF  [CAP0402]  219.58 229.88 0 top
C373  0.1uF  [CAP0402]  284.07 100.95 270 bottom
C374  0.1uF  [CAP0402]  205.74 230.39 180 top
C375  0.1uF  [CAP0402]  239.37 77.03 180 bottom
C376  0.1uF  [CAP0402]  282.55 100.95 270 bottom
C377  0.1uF  [CAP0402]  225.37 243.5 90 bottom
C378  0.1uF  [CAP0402]  245.85 76.01 0 bottom
C379  0.1uF  [CAP0402]  239.37 75.5 0 bottom
C380  0.1uF  [CAP0402]  239.37 73.98 180 bottom
C381  22uF  [CAP0805]  233.58 73.6 180 bottom
C382  0.1uF  [CAP0402]  239.37 72.46 180 bottom
C383  0.1uF  [CAP0402]  243.94 70.93 90 bottom
C384  1uF  [CAP0402]  54.61 227.81 270 bottom
C385  1uF  [CAP0402]  52.45 227.81 90 bottom
C386  1000pF  [CAP0402]  255.4 98.06 0 bottom
C387  1uF  [CAP0402]  124.71 230.39 270 bottom
C388  22uF  [CAP0805]  236.32 36.26 270 top
C389  1uF  [CAP0402]  242.16 45.28 0 bottom
C390  1uF  [CAP0402]  246.48 56.45 270 bottom
C391  0.1uF  [CAP0402]  26.67 229.88 180 bottom
C392  2.2uF  [CAP0402]  246.51 86.63 270 bottom
C393  0.1uF  [CAP0402]  242.8 50.87 0 bottom
C394  0.1uF  [CAP0402]  25.15 227.34 0 bottom
C395  0.1uF  [CAP0402]  246.1 40.2 90 bottom
C396  0.01uF  [CAP0402]  68.58 214.26 90 bottom
C397  0.01uF  [CAP0402]  78.87 211.98 90 bottom
C399  1uF  [CAP0402]  239.75 36.64 90 top
C400  0.01uF  [CAP0402]  78.23 209.69 180 bottom
C401  1uF  [CAP0402]  236.73 40.15 90 bottom
C403  0.01uF  [CAP0402]  67.69 209.31 180 bottom
C404  0.01uF  [CAP0402]  261.49 218.2 90 bottom
C405  0.1uF  [CAP0402]  261.04 213.2 90 bottom
C406  0.1uF  [CAP0402]  238.23 50.87 180 bottom
C407  22pF  [CAP0402]  263.25 49.09 0 bottom
C408  0.01uF  [CAP0402]  253.09 48.07 180 bottom
C409  1uF  [CAP0402]  235.69 47.69 270 bottom
C410  0.1uF  [CAP0402]  74.04 203.98 270 bottom
C411  1uF  [CAP0402]  234.92 52.39 0 bottom
C412  0.1uF  [CAP0402]  253.09 46.37 0 bottom
C413  0.1uF  [CAP0402]  253.09 44.39 0 bottom
C414  10uF  [CAP1210]  269.75 216.3 0 bottom
C415  0.01uF  [CAP0402]  253.09 42.48 180 bottom
C416  0.1uF  [CAP0402]  245.47 50.87 0 bottom
C417  0.22uF  [CAP0402]  248.01 47.82 270 bottom
C418  1uF  [CAP0402]  241.4 40.2 90 bottom
C419  1uF  [CAP0402]  244.45 40.2 90 bottom
C420  0.1uF  [CAP0402]  242.93 36.64 90 bottom
C421  0.1uF  [CAP0402]  241.27 36.64 90 bottom
C422  1uF  [CAP0402]  239.75 36.64 90 bottom
C423  0.1uF  [CAP0402]  236.45 57.85 270 bottom
C424  0.1uF  [CAP0402]  234.16 47.69 270 bottom
C425  0.1uF  [CAP0402]  83.57 197.25 180 bottom
C426  0.1uF  [CAP0402]  66.55 197.12 0 bottom
C427  0.1uF  [CAP0402]  83.44 195.59 180 bottom
C428  0.1uF  [CAP0402]  150.11 181.32 180 bottom
C429  0.1uF  [CAP0402]  126.11 168.54 0 bottom
C430  0.1uF  [CAP0402]  144.02 187.47 270 bottom
C431  0.1uF  [CAP0402]  140.97 187.47 270 bottom
C432  0.1uF  [CAP0402]  137.92 187.47 270 bottom
C433  0.1uF  [CAP0402]  134.87 187.47 270 bottom
C434  0.1uF  [CAP0402]  131.83 187.47 270 bottom
C435  0.01uF  [CAP0402]  84.58 187.85 0 bottom
C436  0.1uF  [CAP0402]  74.68 188.23 90 bottom
C437  0.1uF  [CAP0402]  130.3 187.47 270 bottom
C438  0.1uF  [CAP0402]  126.11 185.31 0 bottom
C439  2.2uF  [CAP0402]  241.68 184.8 180 bottom
C440  0.1uF  [CAP0402]  128.4 180.1 270 bottom
C441  0.01uF  [CAP0402]  103.38 184.55 90 bottom
C442  0.01uF  [CAP0402]  141.88 183.02 0 bottom
C443  0.01uF  [CAP0402]  140.84 180.48 270 bottom
C444  0.01uF  [CAP0402]  137.29 182.01 0 bottom
C445  0.01uF  [CAP0402]  135.13 183.91 180 bottom
C446  0.1uF  [CAP0402]  241.68 183.02 0 bottom
C447  0.1uF  [CAP0402]  126.11 182.26 0 bottom
C448  22uF  [CAP0805]  131.83 183.91 180 bottom
C449  0.01uF  [CAP0402]  137.67 180.35 0 bottom
C450  0.01uF  [CAP0402]  143.76 181.24 0 bottom
C451  330pF  [CAP0402]  246.28 176.67 180 bottom
C452  0.1uF  [CAP0402]  244.14 182.51 90 top
C453  0.01uF  [CAP0402]  102.49 179.47 90 bottom
C454  0.1uF  [CAP0402]  126.11 179.21 0 bottom
C455  0.1uF  [CAP0402]  139.34 184.6 0 bottom
C456  0.01uF  [CAP0402]  142.49 177.43 0 bottom
C457  2.2uF  [CAP0402]  251.59 177.21 0 bottom
C458  0.1uF  [CAP0402]  126.11 176.16 0 bottom
C459  0.1uF  [CAP0402]  250.47 37 0 bottom
C460  0.1uF  [CAP0402]  77.72 176.29 0 bottom
C461  0.1uF  [CAP0402]  72.9 176.29 0 bottom
C462  0.01uF  [CAP0402]  139.19 175.66 0 bottom
C463  10uF  [CAP0805]  234.19 175.91 270 bottom
C464  0.1uF  [CAP0402]  238.38 175.66 270 bottom
C465  0.01uF  [CAP0402]  144.4 175.15 90 bottom
C466  0.1uF  [CAP0402]  251.56 178.81 180 bottom
C467  0.1uF  [CAP0402]  52.73 180.53 0 top
C468  4.7uF  [CAP1206]  256.54 174.64 90 bottom
C469  2.2uF  [CAP0402]  242.82 174.51 0 bottom
C470  0.1uF  [CAP0402]  126.11 173.12 0 bottom
C471  0.1uF  [CAP0402]  254.25 174.15 270 bottom
C472  0.1uF  [CAP0402]  247.68 173.9 0 bottom
C473  0.01uF  [CAP0402]  181.6 198.46 270 bottom
C474  0.01uF  [CAP0402]  142.37 172.86 270 bottom
C475  0.01uF  [CAP0402]  140.08 172.86 270 bottom
C476  0.1uF  [CAP0402]  242.82 172.73 180 bottom
C477  0.01uF  [CAP0402]  135.38 172.35 270 bottom
C478  0.01uF  [CAP0402]  133.73 172.35 270 bottom
C479  10uF  [CAP0805]  234.19 171.34 90 bottom
C480  0.1uF  [CAP0402]  139.45 187.47 270 bottom
C481  0.1uF  [CAP0402]  126.11 177.69 0 bottom
C482  0.1uF  [CAP0402]  126.11 170.07 0 bottom
C483  0.1uF  [CAP0402]  185.28 197.82 180 bottom
C484  0.1uF  [CAP0402]  243.59 161.64 90 bottom
C485  4.7uF  [CAP1206]  246.94 160.62 0 bottom
C486  0.1uF  [CAP0402]  214.66 80.61 90 bottom
C487  0.1uF  [CAP0402]  137.79 168.8 90 bottom
C488  0.01uF  [CAP0402]  142.49 167.91 0 bottom
C489  0.01uF  [CAP0402]  140.21 168.67 90 bottom
C490  0.01uF  [CAP0402]  135.64 168.92 90 bottom
C491  0.01uF  [CAP0402]  133.73 168.92 90 bottom
C492  0.1uF  [CAP0402]  184.4 183.47 0 bottom
C493  0.1uF  [CAP0402]  245.62 167.27 0 bottom
C494  22uF  [CAP0805]  144.14 162.57 90 bottom
C495  0.01uF  [CAP0402]  137.67 165.11 0 bottom
C496  0.01uF  [CAP0402]  145.24 165.52 0 bottom
C498  4.7uF  [CAP1206]  245.24 165.11 180 bottom
C500  0.1uF  [CAP0402]  128.42 164.25 270 bottom
C501  0.01uF  [CAP0402]  142.37 162.96 90 bottom
C502  0.01uF  [CAP0402]  136.91 160.67 90 bottom
C503  0.01uF  [CAP0402]  144.27 159.27 90 bottom
C504  0.1uF  [CAP0402]  242.8 159.2 0 bottom
C505  2.2uF  [CAP0402]  242.82 157.62 180 bottom
C506  0.01uF  [CAP0402]  142.37 157.62 270 bottom
C507  0.01uF  [CAP0402]  140.08 157.62 270 bottom
C508  0.01uF  [CAP0402]  135.64 157.49 270 bottom
C509  0.01uF  [CAP0402]  133.98 158.89 270 bottom
C510  0.1uF  [CAP0402]  139.06 153.3 180 bottom
C511  0.01uF  [CAP0402]  142.24 152.8 0 bottom
C512  0.01uF  [CAP0402]  140.84 150.26 270 bottom
C513  0.01uF  [CAP0402]  136.02 153.3 0 bottom
C514  0.01uF  [CAP0402]  132.97 153.3 180 bottom
C515  22uF  [CAP0805]  147.27 151.93 90 bottom
C516  0.01uF  [CAP0402]  137.67 149.87 0 bottom
C517  0.01uF  [CAP0402]  145.16 151.53 90 bottom
C518  0.01uF  [CAP0402]  273.81 149.75 180 bottom
C519  0.01uF  [CAP0402]  256.29 149.11 180 bottom
C520  0.01uF  [CAP0402]  243.46 148.35 180 bottom
C521  0.1uF  [CAP0402]  129.82 146.52 90 bottom
C522  0.01uF  [CAP0402]  139.27 145.2 180 bottom
C523  0.01uF  [CAP0402]  138.81 141.75 270 bottom
C524  0.01uF  [CAP0402]  144.27 144.49 90 bottom
C525  0.1uF  [CAP0201]  172.39 125.21 90 bottom
C527  0.1uF  [CAP0201]  179.88 128.49 0 bottom
C528  0.01uF  [CAP0402]  141.86 141.75 270 bottom
C529  0.01uF  [CAP0402]  140.33 141.75 270 bottom
C530  0.01uF  [CAP0402]  135.38 141.87 270 bottom
C531  0.01uF  [CAP0402]  133.86 143.65 270 bottom
C532  0.1uF  [CAP0402]  209.93 91.71 270 top
C533  0.01uF  [CAP0402]  243.46 139.33 180 bottom
C534  0.1uF  [CAP0402]  168.27 139.21 270 bottom
C535  0.1uF  [CAP0201]  177.11 122.52 225 bottom
C536  0.1uF  [CAP0201]  172.21 141.49 90 bottom
C537  0.1uF  [CAP0402]  171.32 139.21 270 bottom
C538  0.1uF  [CAP0201]  166.78 134.61 0 bottom
C539  0.1uF  [CAP0201]  166.67 131.76 90 bottom
C540  0.1uF  [CAP0402]  136.4 139.33 0 bottom
C541  0.01uF  [CAP0402]  141.99 139.08 0 bottom
C542  0.01uF  [CAP0402]  141.99 136.41 0 bottom
C543  0.01uF  [CAP0402]  136.4 137.81 0 bottom
C544  0.01uF  [CAP0402]  133.35 137.81 180 bottom
C545  0.01uF  [CAP0402]  255.52 138.19 180 bottom
C546  22uF  [CAP0805]  141.86 134.25 180 bottom
C547  0.01uF  [CAP0402]  137.67 134.63 0 bottom
C548  0.01uF  [CAP0402]  145.29 136.03 90 bottom
C549  0.1uF  [CAP0201]  186.44 126.63 270 bottom
C550  1uF  [CAP0402]  166.75 139.21 90 bottom
C551  0.1uF  [CAP0201]  187.71 126.76 270 bottom
C552  1uF  [CAP0402]  155.04 133.9 180 bottom
C553  0.1uF  [CAP0201]  191.8 104.92 0 bottom
C554  0.1uF  [CAP0402]  137.79 130.72 180 bottom
C555  0.01uF  [CAP0402]  142.49 132.35 0 bottom
C556  0.1uF  [CAP0201]  186.31 123.2 270 bottom
C557  0.1uF  [CAP0201]  155.32 132.73 0 top
C558  0.1uF  [CAP0201]  187.71 120.28 270 bottom
C559  0.01uF  [CAP0402]  137.67 129.17 0 bottom
C560  0.1uF  [CAP0201]  187.71 123.2 270 bottom
C561  0.1uF  [CAP0402]  152.68 129.81 90 bottom
C562  0.1uF  [CAP0201]  186.44 120.16 270 bottom
C563  0.01uF  [CAP0402]  144.14 129.43 90 bottom
C564  0.1uF  [CAP0201]  191.8 106.59 0 bottom
C565  0.1uF  [CAP0402]  154.3 127.4 0 bottom
C566  0.1uF  [CAP0201]  163.96 120.92 90 bottom
C567  0.1uF  [CAP0201]  191.8 105.76 0 bottom
C568  0.01uF  [CAP0402]  140.08 130.57 270 bottom
C569  0.01uF  [CAP0402]  140.08 127.65 0 bottom
C570  0.01uF  [CAP0402]  135.38 126.63 270 bottom
C571  0.01uF  [CAP0402]  133.86 128.54 270 bottom
C572  0.1uF  [CAP0201]  175.72 123.31 270 bottom
C573  0.1uF  [CAP0201]  170.74 120.23 315 bottom
C574  0.1uF  [CAP0201]  162.97 122.77 180 bottom
C575  0.1uF  [CAP0201]  176.33 128.51 90 bottom
C576  0.1uF  [CAP0201]  169.09 120.18 180 bottom
C577  0.1uF  [CAP0201]  183.49 125.49 0 bottom
C578  0.1uF  [CAP0402]  129.62 116.88 90 bottom
C579  0.01uF  [CAP0402]  135.25 123.59 90 bottom
C580  0.01uF  [CAP0402]  133.35 121.43 90 bottom
C581  0.01uF  [CAP0402]  137.54 121.93 90 bottom
C582  22uF  [CAP0805]  143.38 122.32 0 bottom
C583  0.01uF  [CAP0402]  140.84 121.17 90 bottom
C584  0.01uF  [CAP0402]  139.32 123.08 90 bottom
C585  100uF  [CAP1210]  207.7 122.77 90 bottom
C586  0.1uF  [CAP0201]  187.68 112.31 90 bottom
C587  0.1uF  [CAP0201]  175.72 121.88 270 bottom
C588  0.1uF  [CAP0201]  183.67 104.76 90 bottom
C589  0.01uF  [CAP0402]  145.92 120.92 270 bottom
C590  0.1uF  [CAP0201]  186.44 125.11 180 bottom
C591  0.1uF  [CAP0201]  171.98 119.45 180 bottom
C592  0.1uF  [CAP0201]  180.37 120.72 270 bottom
C593  0.1uF  [CAP0201]  177.09 116.35 135 bottom
C594  0.1uF  [CAP0201]  180.37 118.94 90 bottom
C595  0.1uF  [CAP0402]  154.3 124.35 0 bottom
C596  0.1uF  [CAP0402]  192.28 111.27 180 bottom
C597  0.1uF  [CAP0201]  195.96 109.74 180 bottom
C598  0.1uF  [CAP0402]  154.3 124.35 0 top
C599  0.1uF  [CAP0402]  192.28 109.74 180 bottom
C600  1uF  [CAP0402]  196.22 108.22 0 bottom
C601  0.1uF  [CAP0402]  154.3 125.87 180 bottom
C602  0.01uF  [CAP0402]  132.97 119.55 180 bottom
C603  0.01uF  [CAP0402]  140.54 111.17 0 top
C604  0.01uF  [CAP0402]  142.39 113.1 180 bottom
C605  0.01uF  [CAP0402]  141.58 123.84 180 top
C606  0.01uF  [CAP0402]  135.38 110.12 270 bottom
C607  0.01uF  [CAP0402]  132.72 112.66 180 bottom
C608  0.01uF  [CAP0402]  137.79 119.65 0 bottom
C609  0.1uF  [CAP0402]  192.28 108.22 180 bottom
C610  0.1uF  [CAP0402]  129.62 116.88 90 top
C611  0.1uF  [CAP0201]  171.2 122.07 0 bottom
C612  1uF  [CAP0402]  145.67 100.85 180 bottom
C613  0.1uF  [CAP0201]  174.12 104.92 90 bottom
C614  0.1uF  [CAP0201]  179.91 110.07 180 bottom
C615  0.1uF  [CAP0201]  171.83 110 0 bottom
C616  0.1uF  [CAP0201]  169.42 106.06 90 bottom
C617  0.1uF  [CAP0201]  171.2 123.76 0 bottom
C618  0.1uF  [CAP0201]  172.42 103.7 180 bottom
C619  0.1uF  [CAP0201]  177.14 120.94 225 bottom
C620  0.1uF  [CAP0201]  171.2 123.05 0 bottom
C621  0.1uF  [CAP0201]  173.23 123.71 180 bottom
C622  0.1uF  [CAP0402]  210.95 54.37 90 top
C623  0.1uF  [CAP0201]  169.9 112.38 180 bottom
C624  0.1uF  [CAP0201]  173.89 113.15 0 bottom
C625  0.1uF  [CAP0201]  168.88 102.1 90 bottom
C626  0.1uF  [CAP0402]  144.55 96.71 90 bottom
C627  0.1uF  [CAP0201]  180.52 105.91 90 bottom
